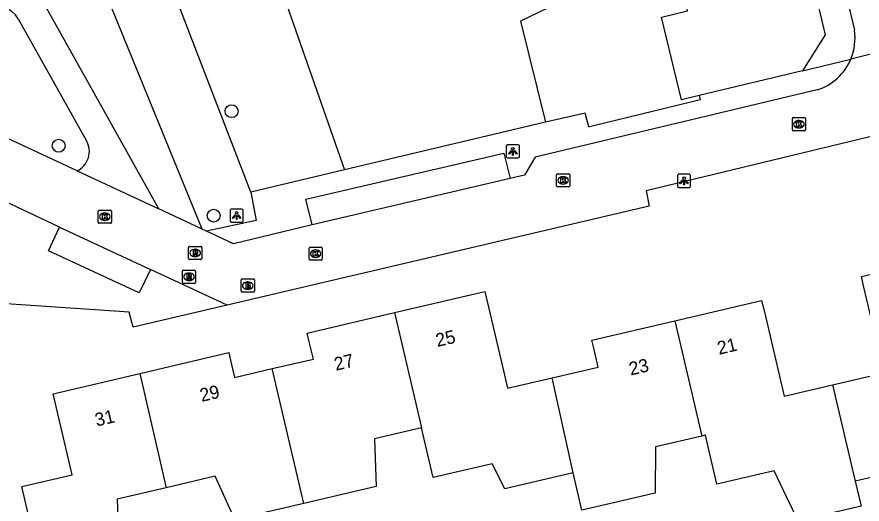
# Model space of a CAD drawing. Extents: x 157793 to 159380, y 380882 to 382313.
# Drawn here: x 158869.3 to 158933.4, y 381228.2 to 381265.2 of the extents above; entities that cross this region are included whole.
import ezdxf

# ---------------------------------------------------------------- set-up
doc = ezdxf.new("R2010")
doc.units = 0
for name, color, linetype in [('IMGEO_Boom', 7, 'Continuous'), ('IMGEO_Brandkraan', 7, 'Continuous'), ('IMGEO_Groenvoorziening', 7, 'Continuous'), ('IMGEO_Kolk', 7, 'Continuous'), ('IMGEO_Lichtpunt', 7, 'Continuous'), ('IMGEO_Pand', 7, 'Continuous'), ('IMGEO_Pand_nummerreeks', 7, 'Continuous'), ('IMGEO_Rijbaan_lokaal_open', 7, 'Continuous'), ('IMGEO_Rioolput', 7, 'Continuous'), ('IMGEO_Voetpad_halfverhard', 7, 'Continuous'), ('IMGEO_Voetpad_open', 7, 'Continuous')]:
    doc.layers.add(name, color=color, linetype=linetype)

msp = doc.modelspace()

# ---------------------------------------------------------------- linework, layer by layer
at = {"layer": 'IMGEO_Boom'}
for centre in [(158885.603, 381258.023), (158872.497, 381255.406), (158884.242, 381250.106)]:
    msp.add_circle(centre, 0.489, dxfattribs=at)
at = {"layer": 'IMGEO_Brandkraan'}
for p, q in [((158886.401, 381245.307), (158887.253, 381245.307)), ((158886.326, 381244.381), (158886.326, 381245.233)), ((158886.814, 381245.087), (158886.839, 381245.087)), ((158887.327, 381245.233), (158887.327, 381244.381)), ((158887.253, 381244.307), (158886.401, 381244.307)), ((158886.837, 381244.527), (158886.812, 381244.527))]:
    msp.add_line(p, q, dxfattribs=at)
for points in [[(158886.401, 381245.307), (158887.253, 381245.307)], [(158886.326, 381244.381), (158886.326, 381245.233)], [(158886.674, 381245.007), (158886.674, 381244.607), (158886.887, 381244.607)], [(158886.905, 381245.007), (158886.674, 381245.007)], [(158886.853, 381244.926), (158886.799, 381244.926), (158886.799, 381244.85)], [(158886.799, 381244.85), (158886.852, 381244.85)], [(158886.861, 381244.774), (158886.799, 381244.774), (158886.799, 381244.693)], [(158886.799, 381244.693), (158886.861, 381244.693)], [(158887.327, 381245.233), (158887.327, 381244.381)], [(158887.253, 381244.307), (158886.401, 381244.307)]]:
    msp.add_lwpolyline(points, dxfattribs=at)
for centre, radius, start, end in [((158886.403, 381245.231), 0.0765, 91.55205, 178.44795), ((158886.403, 381245.231), 0.0765, 91.55205, 178.44795), ((158887.251, 381245.231), 0.0765, 1.55205, 88.44795), ((158887.251, 381245.231), 0.0765, 1.55205, 88.44795), ((158886.854, 381244.888), 0.0379, 267.82845, 90.93552), ((158886.862, 381244.733), 0.0404, 269.87594, 90.50774), ((158886.893, 381244.858), 0.251, 268.66757, 293.53466), ((158886.909, 381244.862), 0.145, 59.4692, 91.53667), ((158886.934, 381244.909), 0.0922, 285.51372, 58.15012), ((158886.939, 381244.717), 0.105, 301.31148, 78.98903), ((158886.403, 381244.383), 0.0765, 181.55205, 268.44795), ((158886.403, 381244.383), 0.0765, 181.55205, 268.44795), ((158887.251, 381244.383), 0.0765, 271.55205, 358.44795), ((158887.251, 381244.383), 0.0765, 271.55205, 358.44795)]:
    msp.add_arc(centre, radius, start, end, dxfattribs=at)
for centre, major_axis, ratio, start_param, end_param in [((158886.813, 381244.807), (-0.387, 0.002), 0.722429, 4.712389, 7.853982), ((158886.838, 381244.807), (-0.39, 0.002), 0.717154, 1.570796, 4.712389)]:
    msp.add_ellipse(centre, major_axis=major_axis, ratio=ratio, start_param=start_param, end_param=end_param, dxfattribs=at)
at = {"layer": 'IMGEO_Groenvoorziening'}
for points in [[(158876.043, 381295.307), (158881.496, 381273.953), (158886.588, 381275.264), (158894.165, 381253.568)], [(158887.053, 381251.877), (158871.471, 381292.36)], [(158883.377, 381249.09), (158866.882, 381289.403)]]:
    msp.add_lwpolyline(points, dxfattribs=at)
at = {"layer": 'IMGEO_Kolk'}
for p, q in [((158928.089, 381256.61), (158928.089, 381257.462)), ((158928.164, 381257.536), (158929.016, 381257.536)), ((158929.09, 381257.462), (158929.09, 381256.61)), ((158928.577, 381257.316), (158928.602, 381257.316)), ((158929.016, 381256.536), (158928.164, 381256.536)), ((158928.6, 381256.756), (158928.575, 381256.756)), ((158910.222, 381252.356), (158910.222, 381253.208)), ((158910.297, 381253.282), (158911.149, 381253.282)), ((158910.71, 381253.062), (158910.735, 381253.062)), ((158911.223, 381253.208), (158911.223, 381252.356)), ((158910.733, 381252.502), (158910.708, 381252.502)), ((158911.149, 381252.282), (158910.297, 381252.282)), ((158875.495, 381249.602), (158875.495, 381250.454)), ((158875.57, 381250.528), (158876.422, 381250.528)), ((158876.496, 381250.454), (158876.496, 381249.602)), ((158876.006, 381249.748), (158875.981, 381249.748)), ((158875.983, 381250.308), (158876.008, 381250.308)), ((158876.422, 381249.528), (158875.57, 381249.528)), ((158891.471, 381246.799), (158891.471, 381247.651)), ((158891.546, 381247.725), (158892.398, 381247.725)), ((158891.959, 381247.505), (158891.984, 381247.505)), ((158892.472, 381247.651), (158892.472, 381246.799)), ((158892.398, 381246.725), (158891.546, 381246.725)), ((158891.982, 381246.945), (158891.957, 381246.945))]:
    msp.add_line(p, q, dxfattribs=at)
for points in [[(158928.089, 381256.61), (158928.089, 381257.462)], [(158928.164, 381257.536), (158929.016, 381257.536)], [(158929.09, 381257.462), (158929.09, 381256.61)], [(158928.41, 381257.236), (158928.533, 381257.236), (158928.533, 381257.085), (158928.663, 381257.236), (158928.827, 381257.236), (158928.681, 381257.085), (158928.834, 381256.836), (158928.682, 381256.836), (158928.597, 381257), (158928.533, 381256.933), (158928.533, 381256.836), (158928.41, 381256.836), (158928.41, 381257.236)], [(158929.016, 381256.536), (158928.164, 381256.536)], [(158910.222, 381252.356), (158910.222, 381253.208)], [(158910.297, 381253.282), (158911.149, 381253.282)], [(158910.543, 381252.982), (158910.666, 381252.982), (158910.666, 381252.831), (158910.796, 381252.982), (158910.96, 381252.982), (158910.814, 381252.831), (158910.967, 381252.582), (158910.815, 381252.582), (158910.73, 381252.746), (158910.666, 381252.679), (158910.666, 381252.582), (158910.543, 381252.582), (158910.543, 381252.982)], [(158911.223, 381253.208), (158911.223, 381252.356)], [(158911.149, 381252.282), (158910.297, 381252.282)], [(158875.495, 381249.602), (158875.495, 381250.454)], [(158875.57, 381250.528), (158876.422, 381250.528)], [(158876.496, 381250.454), (158876.496, 381249.602)], [(158875.816, 381250.228), (158875.939, 381250.228), (158875.939, 381250.077), (158876.069, 381250.228), (158876.233, 381250.228), (158876.087, 381250.077), (158876.24, 381249.828), (158876.088, 381249.828), (158876.003, 381249.992), (158875.939, 381249.925), (158875.939, 381249.828), (158875.816, 381249.828), (158875.816, 381250.228)], [(158876.422, 381249.528), (158875.57, 381249.528)], [(158891.471, 381246.799), (158891.471, 381247.651)], [(158891.546, 381247.725), (158892.398, 381247.725)], [(158891.792, 381247.425), (158891.915, 381247.425), (158891.915, 381247.274), (158892.045, 381247.425), (158892.209, 381247.425), (158892.063, 381247.274), (158892.216, 381247.025), (158892.064, 381247.025), (158891.979, 381247.189), (158891.915, 381247.122), (158891.915, 381247.025), (158891.792, 381247.025), (158891.792, 381247.425)], [(158892.472, 381247.651), (158892.472, 381246.799)], [(158892.398, 381246.725), (158891.546, 381246.725)]]:
    msp.add_lwpolyline(points, dxfattribs=at)
for centre, start, end in [((158928.166, 381257.46), 91.55205, 178.44795), ((158928.166, 381257.46), 91.55205, 178.44795), ((158929.014, 381257.46), 1.55205, 88.44795), ((158929.014, 381257.46), 1.55205, 88.44795), ((158928.166, 381256.612), 181.55205, 268.44795), ((158928.166, 381256.612), 181.55205, 268.44795), ((158929.014, 381256.612), 271.55205, 358.44795), ((158929.014, 381256.612), 271.55205, 358.44795), ((158910.299, 381253.206), 91.55205, 178.44795), ((158910.299, 381253.206), 91.55205, 178.44795), ((158911.147, 381253.206), 1.55205, 88.44795), ((158911.147, 381253.206), 1.55205, 88.44795), ((158910.299, 381252.358), 181.55205, 268.44795), ((158910.299, 381252.358), 181.55205, 268.44795), ((158911.147, 381252.358), 271.55205, 358.44795), ((158911.147, 381252.358), 271.55205, 358.44795), ((158875.572, 381250.452), 91.55205, 178.44795), ((158875.572, 381250.452), 91.55205, 178.44795), ((158876.42, 381250.452), 1.55205, 88.44795), ((158876.42, 381250.452), 1.55205, 88.44795), ((158875.572, 381249.604), 181.55205, 268.44795), ((158875.572, 381249.604), 181.55205, 268.44795), ((158876.42, 381249.604), 271.55205, 358.44795), ((158876.42, 381249.604), 271.55205, 358.44795), ((158891.548, 381247.649), 91.55205, 178.44795), ((158891.548, 381247.649), 91.55205, 178.44795), ((158892.396, 381247.649), 1.55205, 88.44795), ((158892.396, 381247.649), 1.55205, 88.44795), ((158891.548, 381246.801), 181.55205, 268.44795), ((158891.548, 381246.801), 181.55205, 268.44795), ((158892.396, 381246.801), 271.55205, 358.44795), ((158892.396, 381246.801), 271.55205, 358.44795)]:
    msp.add_arc(centre, 0.0765, start, end, dxfattribs=at)
for centre, major_axis, ratio, start_param, end_param in [((158928.576, 381257.036), (-0.387, 0.002), 0.722429, 4.712389, 7.853982), ((158928.601, 381257.036), (-0.39, 0.002), 0.717154, 1.570796, 4.712389), ((158910.709, 381252.782), (-0.387, 0.002), 0.722429, 4.712389, 7.853982), ((158910.734, 381252.782), (-0.39, 0.002), 0.717154, 1.570796, 4.712389), ((158875.982, 381250.028), (-0.387, 0.002), 0.722429, 4.712389, 7.853982), ((158876.007, 381250.028), (-0.39, 0.002), 0.717154, 1.570796, 4.712389), ((158891.958, 381247.225), (-0.387, 0.002), 0.722429, 4.712389, 7.853982), ((158891.983, 381247.225), (-0.39, 0.002), 0.717154, 1.570796, 4.712389)]:
    msp.add_ellipse(centre, major_axis=major_axis, ratio=ratio, start_param=start_param, end_param=end_param, dxfattribs=at)
at = {"layer": 'IMGEO_Lichtpunt'}
for p, q in [((158906.417, 381255.383), (158906.417, 381254.576)), ((158906.417, 381255.383), (158906.417, 381254.576)), ((158907.319, 381255.478), (158906.511, 381255.478)), ((158907.319, 381255.478), (158906.511, 381255.478)), ((158907.413, 381254.576), (158907.413, 381255.383)), ((158907.413, 381254.576), (158907.413, 381255.383)), ((158906.511, 381254.482), (158907.319, 381254.482)), ((158906.511, 381254.482), (158907.319, 381254.482)), ((158919.387, 381253.146), (158919.387, 381252.339)), ((158919.387, 381253.146), (158919.387, 381252.339)), ((158920.289, 381253.241), (158919.481, 381253.241)), ((158920.289, 381253.241), (158919.481, 381253.241)), ((158920.383, 381252.339), (158920.383, 381253.146)), ((158920.383, 381252.339), (158920.383, 381253.146)), ((158919.481, 381252.245), (158920.289, 381252.245)), ((158919.481, 381252.245), (158920.289, 381252.245)), ((158885.487, 381250.515), (158885.487, 381249.708)), ((158885.487, 381250.515), (158885.487, 381249.708)), ((158886.389, 381250.61), (158885.581, 381250.61)), ((158886.389, 381250.61), (158885.581, 381250.61)), ((158886.483, 381249.708), (158886.483, 381250.515)), ((158886.483, 381249.708), (158886.483, 381250.515)), ((158885.581, 381249.614), (158886.389, 381249.614)), ((158885.581, 381249.614), (158886.389, 381249.614))]:
    msp.add_line(p, q, dxfattribs=at)
for points in [[(158906.791, 381255.047), (158906.83, 381255.019), (158906.642, 381254.757), (158906.604, 381254.784), (158906.791, 381255.047)], [(158906.893, 381254.999), (158906.94, 381254.999), (158906.94, 381254.677), (158906.893, 381254.677), (158906.893, 381254.999)], [(158907.003, 381255.019), (158907.041, 381255.046), (158907.228, 381254.784), (158907.189, 381254.756), (158907.003, 381255.019)], [(158919.761, 381252.81), (158919.8, 381252.782), (158919.612, 381252.52), (158919.574, 381252.547), (158919.761, 381252.81)], [(158919.863, 381252.762), (158919.91, 381252.762), (158919.91, 381252.44), (158919.863, 381252.44), (158919.863, 381252.762)], [(158919.973, 381252.782), (158920.011, 381252.809), (158920.198, 381252.547), (158920.159, 381252.519), (158919.973, 381252.782)], [(158885.861, 381250.179), (158885.9, 381250.151), (158885.712, 381249.889), (158885.674, 381249.916), (158885.861, 381250.179)], [(158885.963, 381250.131), (158886.01, 381250.131), (158886.01, 381249.809), (158885.963, 381249.809), (158885.963, 381250.131)], [(158886.073, 381250.151), (158886.111, 381250.178), (158886.298, 381249.916), (158886.259, 381249.888), (158886.073, 381250.151)]]:
    msp.add_lwpolyline(points, dxfattribs=at)
for centre in [(158906.916, 381255.181), (158919.886, 381252.944), (158885.986, 381250.313)]:
    msp.add_circle(centre, 0.0994, dxfattribs=at)
for centre, start, end in [((158906.511, 381255.383), 90, 180), ((158906.511, 381255.383), 90, 180), ((158907.319, 381255.383), 0, 90), ((158907.319, 381255.383), 0, 90), ((158906.511, 381254.576), 180, 270), ((158906.511, 381254.576), 180, 270), ((158907.319, 381254.576), 270, 0), ((158907.319, 381254.576), 270, 360), ((158919.481, 381253.146), 90, 180), ((158919.481, 381253.146), 90, 180), ((158920.289, 381253.146), 0, 90), ((158920.289, 381253.146), 0, 90), ((158919.481, 381252.339), 180, 270), ((158919.481, 381252.339), 180, 270), ((158920.289, 381252.339), 270, 0), ((158920.289, 381252.339), 270, 360), ((158885.581, 381250.515), 90, 180), ((158885.581, 381250.515), 90, 180), ((158886.389, 381250.515), 0, 90), ((158886.389, 381250.515), 0, 90), ((158885.581, 381249.708), 180, 270), ((158885.581, 381249.708), 180, 270), ((158886.389, 381249.708), 270, 0), ((158886.389, 381249.708), 270, 360)]:
    msp.add_arc(centre, 0.0946, start, end, dxfattribs=at)
at = {"layer": 'IMGEO_Pand'}
for points in [[(158921.031, 381259.217), (158919.7, 381258.891), (158918.166, 381265.156), (158920.151, 381265.642), (158918.602, 381271.966)], [(158909.91, 381269.837), (158910.746, 381266.422), (158907.497, 381264.86), (158909.376, 381257.183)], [(158921.031, 381259.217), (158921.11, 381258.892), (158920.511, 381258.746), (158912.708, 381256.844), (158912.658, 381256.832), (158912.401, 381257.886), (158909.376, 381257.183)], [(158931.141, 381237.283), (158934.822, 381238.147), (158935.039, 381238.198), (158933.515, 381244.695), (158933.325, 381245.501), (158939.683, 381246.994)], [(158897.945, 381242.758), (158904.795, 381244.363), (158906.206, 381238.351), (158906.518, 381237.023), (158909.884, 381237.814)], [(158919.193, 381242.143), (158925.762, 381243.685), (158925.942, 381242.917), (158927.467, 381236.42), (158931.141, 381237.283)], [(158888.688, 381238.512), (158891.799, 381239.242), (158891.491, 381240.55), (158891.337, 381241.207), (158897.945, 381242.758)], [(158897.945, 381242.758), (158899.998, 381234.017)], [(158909.884, 381237.814), (158913.382, 381238.635), (158913.07, 381239.963), (158912.905, 381240.666), (158919.193, 381242.143)], [(158919.193, 381242.143), (158921.239, 381233.398)], [(158878.662, 381238.145), (158885.39, 381239.725), (158885.526, 381239.15), (158885.833, 381237.842), (158888.688, 381238.512)], [(158891.082, 381228.301), (158888.688, 381238.512)], [(158941.737, 381238.216), (158938.32, 381237.413), (158938.309, 381231.254), (158932.856, 381229.974)], [(158880.64, 381229.489), (158876.938, 381228.62), (158877.149, 381222.493), (158871.663, 381221.205), (158869.698, 381229.576), (158873.524, 381230.474), (158872.085, 381236.6), (158878.662, 381238.145)], [(158878.662, 381238.145), (158880.64, 381229.489)], [(158911.475, 381230.618), (158909.884, 381237.814)], [(158931.141, 381237.283), (158932.732, 381230.504), (158932.856, 381229.974)], [(158899.998, 381234.017), (158896.429, 381233.18), (158896.546, 381229.584), (158891.082, 381228.301)], [(158911.475, 381230.618), (158906.304, 381229.404), (158905.347, 381231.306), (158900.878, 381230.258), (158899.998, 381234.017)], [(158921.239, 381233.398), (158917.732, 381232.575), (158917.69, 381229.084), (158912.141, 381227.781), (158911.475, 381230.618)], [(158932.856, 381229.974), (158933.299, 381228.088), (158928.539, 381226.97), (158927.673, 381228.757), (158926.701, 381230.764), (158922.379, 381229.749), (158921.51, 381233.462), (158921.239, 381233.398)], [(158891.082, 381228.301), (158885.851, 381227.073), (158884.349, 381230.36), (158880.64, 381229.489)]]:
    msp.add_lwpolyline(points, dxfattribs=at)
at = {"layer": 'IMGEO_Rijbaan_lokaal_open'}
for points in [[(158931.008, 381271.67), (158932.796, 381264.164)], [(158968.906, 381264.456), (158957.537, 381261.722), (158957.278, 381262.898), (158937.248, 381258.103), (158937.52, 381256.931), (158917.019, 381252), (158917.231, 381250.819), (158885.275, 381243.32)], [(158939.738, 381263.77), (158932.526, 381261.978)], [(158873.895, 381253.511), (158859.641, 381260.157)], [(158929.974, 381259.644), (158908.607, 381254.538), (158907.805, 381253.185), (158906.699, 381252.92)], [(158872.554, 381249.232), (158856.241, 381256.942)], [(158873.895, 381253.511), (158880.077, 381250.629)], [(158906.699, 381252.92), (158891.703, 381249.403)], [(158883.377, 381249.09), (158880.077, 381250.629)], [(158872.554, 381249.232), (158879.45, 381246.024)], [(158891.703, 381249.403), (158885.759, 381247.97), (158883.703, 381248.938)], [(158883.703, 381248.938), (158883.377, 381249.09)], [(158885.275, 381243.32), (158879.45, 381246.024)]]:
    msp.add_lwpolyline(points, dxfattribs=at)
for centre, radius, start, end in [((158928.752, 381263.554), 4.09, 337.3369, 8.58085), ((158928.741, 381263.554), 4.1, 287.49926, 337.39137)]:
    msp.add_arc(centre, radius, start, end, dxfattribs=at)
at = {"layer": 'IMGEO_Rioolput'}
for p, q in [((158882.348, 381246.853), (158882.348, 381247.705)), ((158882.423, 381247.779), (158883.275, 381247.779)), ((158882.836, 381247.559), (158882.861, 381247.559)), ((158883.349, 381247.705), (158883.349, 381246.853)), ((158883.275, 381246.779), (158882.423, 381246.779)), ((158882.859, 381246.999), (158882.834, 381246.999)), ((158881.871, 381245.046), (158881.871, 381245.898)), ((158881.946, 381245.972), (158882.798, 381245.972)), ((158882.872, 381245.898), (158882.872, 381245.046)), ((158882.359, 381245.752), (158882.384, 381245.752)), ((158882.798, 381244.972), (158881.946, 381244.972)), ((158882.382, 381245.192), (158882.357, 381245.192))]:
    msp.add_line(p, q, dxfattribs=at)
for points in [[(158882.348, 381246.853), (158882.348, 381247.705)], [(158882.423, 381247.779), (158883.275, 381247.779)], [(158882.937, 381247.477), (158882.685, 381247.479), (158882.685, 381247.079)], [(158882.685, 381247.079), (158882.809, 381247.079), (158882.809, 381247.241), (158882.82, 381247.241)], [(158882.863, 381247.398), (158882.809, 381247.398), (158882.809, 381247.317)], [(158882.809, 381247.317), (158882.861, 381247.317)], [(158882.867, 381247.212), (158882.938, 381247.079), (158883.078, 381247.079), (158883.013, 381247.205)], [(158883.349, 381247.705), (158883.349, 381246.853)], [(158883.275, 381246.779), (158882.423, 381246.779)], [(158881.871, 381245.046), (158881.871, 381245.898)], [(158881.946, 381245.972), (158882.798, 381245.972)], [(158882.872, 381245.898), (158882.872, 381245.046)], [(158882.46, 381245.67), (158882.208, 381245.672), (158882.208, 381245.272)], [(158882.208, 381245.272), (158882.332, 381245.272), (158882.332, 381245.434), (158882.343, 381245.434)], [(158882.386, 381245.591), (158882.332, 381245.591), (158882.332, 381245.51)], [(158882.332, 381245.51), (158882.384, 381245.51)], [(158882.39, 381245.405), (158882.461, 381245.272), (158882.601, 381245.272), (158882.536, 381245.398)], [(158882.798, 381244.972), (158881.946, 381244.972)]]:
    msp.add_lwpolyline(points, dxfattribs=at)
for centre, radius, start, end in [((158882.425, 381247.703), 0.0765, 91.55205, 178.44795), ((158882.425, 381247.703), 0.0765, 91.55205, 178.44795), ((158882.819, 381247.188), 0.0533, 26.02933, 88.69889), ((158882.845, 381247.506), 0.19, 274.7715, 282.96867), ((158882.869, 381247.302), 0.0964, 77.00612, 93.18647), ((158882.883, 381247.359), 0.0378, 276.66336, 79.67722), ((158882.936, 381247.367), 0.109, 350.36119, 89.41601), ((158882.934, 381247.367), 0.112, 277.58423, 350.98172), ((158882.918, 381247.152), 0.108, 29.51342, 73.79051), ((158883.273, 381247.703), 0.0765, 1.55205, 88.44795), ((158883.273, 381247.703), 0.0765, 1.55205, 88.44795), ((158882.425, 381246.855), 0.0765, 181.55205, 268.44795), ((158882.425, 381246.855), 0.0765, 181.55205, 268.44795), ((158883.273, 381246.855), 0.0765, 271.55205, 358.44795), ((158883.273, 381246.855), 0.0765, 271.55205, 358.44795), ((158881.948, 381245.896), 0.0765, 91.55205, 178.44795), ((158881.948, 381245.896), 0.0765, 91.55205, 178.44795), ((158882.796, 381245.896), 0.0765, 1.55205, 88.44795), ((158882.796, 381245.896), 0.0765, 1.55205, 88.44795), ((158882.342, 381245.381), 0.0533, 26.02933, 88.69889), ((158882.368, 381245.699), 0.19, 274.7715, 282.96867), ((158882.392, 381245.495), 0.0964, 77.00612, 93.18647), ((158882.406, 381245.552), 0.0378, 276.66336, 79.67722), ((158882.459, 381245.56), 0.109, 350.36119, 89.41601), ((158882.457, 381245.56), 0.112, 277.58423, 350.98172), ((158882.441, 381245.345), 0.108, 29.51342, 73.79051), ((158881.948, 381245.048), 0.0765, 181.55205, 268.44795), ((158881.948, 381245.048), 0.0765, 181.55205, 268.44795), ((158882.796, 381245.048), 0.0765, 271.55205, 358.44795), ((158882.796, 381245.048), 0.0765, 271.55205, 358.44795)]:
    msp.add_arc(centre, radius, start, end, dxfattribs=at)
for centre, major_axis, ratio, start_param, end_param in [((158882.835, 381247.279), (-0.387, 0.002), 0.722429, 4.712389, 7.853982), ((158882.86, 381247.279), (-0.39, 0.002), 0.717154, 1.570796, 4.712389), ((158882.358, 381245.472), (-0.387, 0.002), 0.722429, 4.712389, 7.853982), ((158882.383, 381245.472), (-0.39, 0.002), 0.717154, 1.570796, 4.712389)]:
    msp.add_ellipse(centre, major_axis=major_axis, ratio=ratio, start_param=start_param, end_param=end_param, dxfattribs=at)
at = {"layer": 'IMGEO_Voetpad_halfverhard'}
for points in [[(158880.077, 381250.629), (158861.545, 381283.771)], [(158869.431, 381265.023), (158874.603, 381255.783)]]:
    msp.add_lwpolyline(points, dxfattribs=at)
for centre, radius, start, end in [((158867.749, 381264.042), 1.947, 30.26668, 114.39122), ((158873.218, 381254.968), 1.607, 294.92005, 30.46382)]:
    msp.add_arc(centre, radius, start, end, dxfattribs=at)
at = {"layer": 'IMGEO_Voetpad_open'}
for points in [[(158904.835, 381302.315), (158906.056, 381302.59), (158915.099, 381292.501), (158916.819, 381292.901), (158922.457, 381287.839), (158923.351, 381283.996), (158924.607, 381284.354), (158926.949, 381274.326), (158927.996, 381274.676), (158930.584, 381263.801), (158928.86, 381261.071)], [(158928.86, 381261.071), (158932.526, 381261.978)], [(158928.86, 381261.071), (158921.031, 381259.217)], [(158909.376, 381257.183), (158894.165, 381253.568)], [(158891.703, 381249.403), (158891.226, 381251.364), (158906.227, 381254.847), (158906.699, 381252.92)], [(158894.165, 381253.568), (158887.053, 381251.877)], [(158887.053, 381251.877), (158887.458, 381249.736), (158883.703, 381248.938)], [(158879.45, 381246.024), (158878.601, 381244.256), (158871.717, 381247.43), (158872.554, 381249.232)], [(158885.275, 381243.32), (158878.143, 381241.655), (158877.854, 381242.8), (158866.657, 381243.554), (158866.752, 381245.951)]]:
    msp.add_lwpolyline(points, dxfattribs=at)

# ---------------------------------------------------------------- texts
at = {"layer": 'IMGEO_Pand_nummerreeks'}
for s, rotation, p in [('25', 13.21241, (158901.195, 381240.152)), ('21', 13.21241, (158922.532, 381239.558)), ('27', 13.2091, (158893.503, 381238.346)), ('23', 13.21433, (158915.846, 381237.988)), ('29', 13.21311, (158883.326, 381235.984)), ('31', 13.21311, (158875.377, 381234.117))]:
    msp.add_text(s, height=1, rotation=rotation, dxfattribs=at).set_placement(p)

doc.saveas('drawing.dxf')
